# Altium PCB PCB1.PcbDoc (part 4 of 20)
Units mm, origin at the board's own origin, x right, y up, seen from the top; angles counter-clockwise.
Board outline 294.51 x 138.18 mm, 12 copper layers (Top Layer 1 _Signal, L2_GND, L3_Signals, L4_GND, L5_POWER, L6_Signals, L7_GND, L8_Signals, L9_GND, L10_POWER, L11_GND, Bottom Layer_Signals), stack 1.788 mm thick; 1254 components, 836 nets, 5699 pads, 2073 vias.
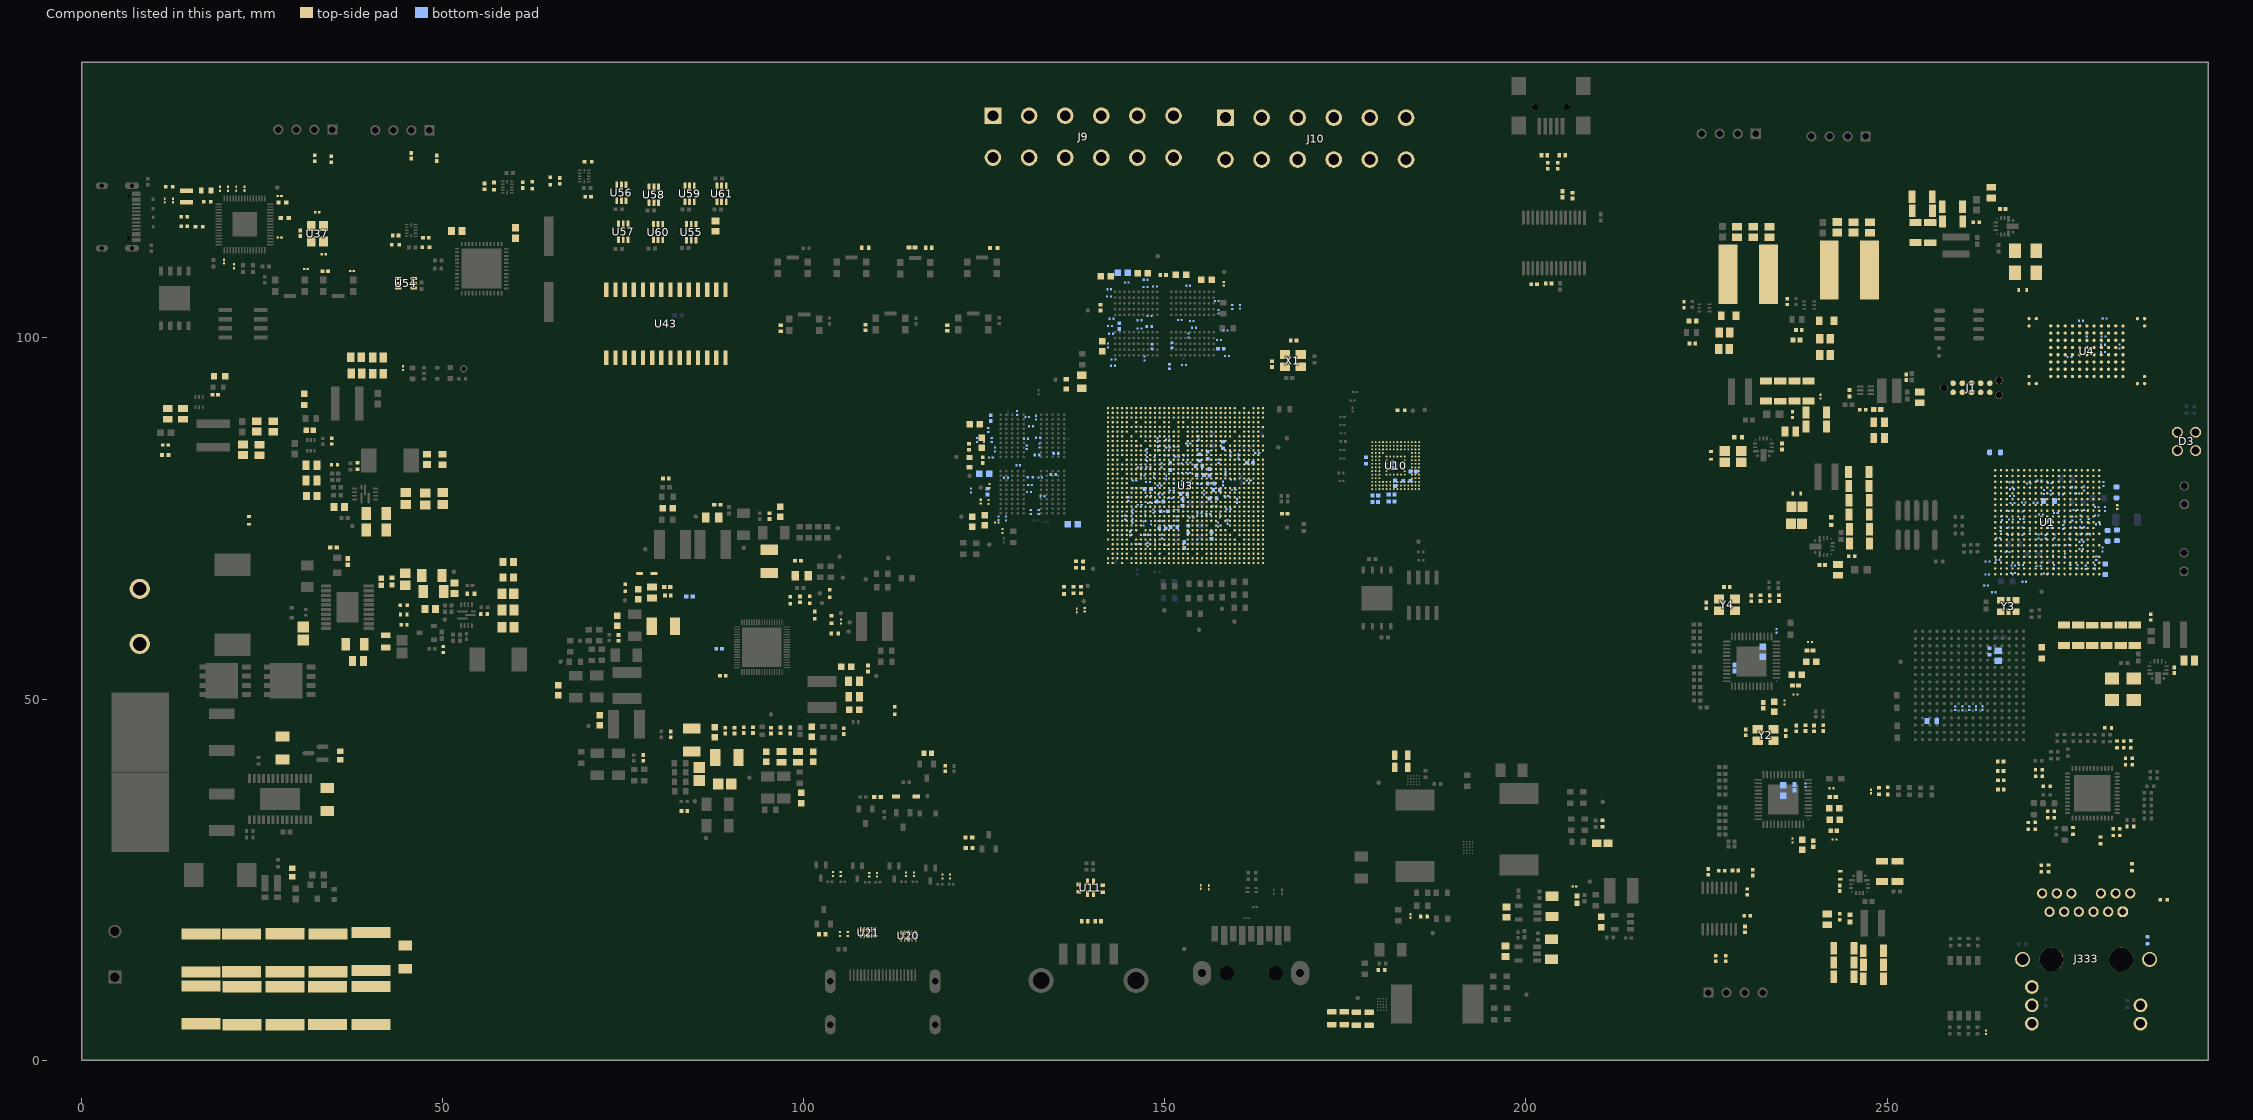
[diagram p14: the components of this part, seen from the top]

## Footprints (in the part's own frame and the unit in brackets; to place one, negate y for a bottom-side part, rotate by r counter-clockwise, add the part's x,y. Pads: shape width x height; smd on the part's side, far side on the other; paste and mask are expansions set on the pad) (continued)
BGA1088C65P34X34_2300X2300X204N [mm]
  round 0.32 smd mask-2539.97: A1(-10.725,10.725) A2(-10.075,10.725) A3(-9.425,10.725) A4(-8.775,10.725) A5(-8.125,10.725) A6(-7.475,10.725) A7(-6.825,10.725) A8(-6.175,10.725) A9(-5.525,10.725) A10(-4.875,10.725) A11(-4.225,10.725) A12(-3.575,10.725) A13(-2.925,10.725) A14(-2.275,10.725) A15(-1.625,10.725) A16(-0.975,10.725) A17(-0.325,10.725) A18(0.325,10.725) A19(0.975,10.725) A20(1.625,10.725) A21(2.275,10.725) A22(2.925,10.725) A23(3.575,10.725) A24(4.225,10.725) A25(4.875,10.725) A26(5.525,10.725) A27(6.175,10.725) A28(6.825,10.725) A30(8.125,10.725) A32(9.425,10.725) A33(10.075,10.725) A34(10.725,10.725) AA1(-10.725,-2.275) AA2(-10.075,-2.275) AA3(-9.425,-2.275) AA4(-8.775,-2.275) AA5(-8.125,-2.275) AA6(-7.475,-2.275) AA7(-6.825,-2.275) AA8(-6.175,-2.275) AA9(-5.525,-2.275) AA10(-4.875,-2.275) AA11(-4.225,-2.275) AA12(-3.575,-2.275) AA13(-2.925,-2.275) AA14(-2.275,-2.275) AA15(-1.625,-2.275) AA16(-0.975,-2.275) AA17(-0.325,-2.275) AA18(0.325,-2.275) AA19(0.975,-2.275) AA20(1.625,-2.275) AA21(2.275,-2.275) AA22(2.925,-2.275) AA23(3.575,-2.275) AA24(4.225,-2.275) AA25(4.875,-2.275) AA26(5.525,-2.275) AA27(6.175,-2.275) AA28(6.825,-2.275) AA29(7.475,-2.275) AA30(8.125,-2.275) AA31(8.775,-2.275) AA32(9.425,-2.275) AA33(10.075,-2.275) AA34(10.725,-2.275) AB1(-10.725,-2.925) AB2(-10.075,-2.925) AB3(-9.425,-2.925) AB4(-8.775,-2.925) AB5(-8.125,-2.925) AB6(-7.475,-2.925) AB7(-6.825,-2.925) AB8(-6.175,-2.925) AB9(-5.525,-2.925) AB10(-4.875,-2.925) AB11(-4.225,-2.925) AB12(-3.575,-2.925) AB13(-2.925,-2.925) AB14(-2.275,-2.925) AB15(-1.625,-2.925) AB16(-0.975,-2.925) AB17(-0.325,-2.925) AB18(0.325,-2.925) AB19(0.975,-2.925) AB20(1.625,-2.925) AB21(2.275,-2.925) AB22(2.925,-2.925) AB23(3.575,-2.925) AB24(4.225,-2.925) AB25(4.875,-2.925) AB26(5.525,-2.925) AB27(6.175,-2.925) AB28(6.825,-2.925) AB29(7.475,-2.925) AB30(8.125,-2.925) AB31(8.775,-2.925) AB32(9.425,-2.925) AB33(10.075,-2.925) AB34(10.725,-2.925) AC1(-10.725,-3.575) AC2(-10.075,-3.575) AC3(-9.425,-3.575) AC4(-8.775,-3.575) AC5(-8.125,-3.575) AC6(-7.475,-3.575) AC7(-6.825,-3.575) AC8(-6.175,-3.575) AC9(-5.525,-3.575) AC10(-4.875,-3.575) AC11(-4.225,-3.575) AC12(-3.575,-3.575) AC13(-2.925,-3.575) AC14(-2.275,-3.575) AC15(-1.625,-3.575) AC16(-0.975,-3.575) AC17(-0.325,-3.575) AC18(0.325,-3.575) AC19(0.975,-3.575) AC20(1.625,-3.575) AC21(2.275,-3.575) AC22(2.925,-3.575) AC23(3.575,-3.575) AC24(4.225,-3.575) AC25(4.875,-3.575) AC26(5.525,-3.575) AC27(6.175,-3.575) AC28(6.825,-3.575) AC29(7.475,-3.575) AC30(8.125,-3.575) AC31(8.775,-3.575) AC32(9.425,-3.575) AC33(10.075,-3.575) AC34(10.725,-3.575) AD1(-10.725,-4.225) AD2(-10.075,-4.225) AD3(-9.425,-4.225) AD4(-8.775,-4.225) AD5(-8.125,-4.225) AD6(-7.475,-4.225) AD7(-6.825,-4.225) AD8(-6.175,-4.225) AD9(-5.525,-4.225) AD10(-4.875,-4.225) AD11(-4.225,-4.225) AD12(-3.575,-4.225) AD13(-2.925,-4.225) AD14(-2.275,-4.225) AD15(-1.625,-4.225) AD16(-0.975,-4.225) AD17(-0.325,-4.225) AD18(0.325,-4.225) AD19(0.975,-4.225) AD20(1.625,-4.225) AD21(2.275,-4.225) AD22(2.925,-4.225) AD23(3.575,-4.225) AD24(4.225,-4.225) AD25(4.875,-4.225) AD26(5.525,-4.225) AD27(6.175,-4.225) AD28(6.825,-4.225) AD29(7.475,-4.225) AD30(8.125,-4.225) AD31(8.775,-4.225) AD32(9.425,-4.225) AD33(10.075,-4.225) AD34(10.725,-4.225) AE1(-10.725,-4.875) AE2(-10.075,-4.875) AE3(-9.425,-4.875) AE4(-8.775,-4.875) AE5(-8.125,-4.875) AE6(-7.475,-4.875) AE7(-6.825,-4.875) AE8(-6.175,-4.875) AE9(-5.525,-4.875) AE11(-4.225,-4.875) AE12(-3.575,-4.875) AE13(-2.925,-4.875) AE14(-2.275,-4.875) AE15(-1.625,-4.875) AE16(-0.975,-4.875) AE18(0.325,-4.875) AE19(0.975,-4.875) AE20(1.625,-4.875) AE21(2.275,-4.875) AE22(2.925,-4.875) AE23(3.575,-4.875) AE24(4.225,-4.875) AE26(5.525,-4.875) AE27(6.175,-4.875) AE28(6.825,-4.875) AE29(7.475,-4.875) AE30(8.125,-4.875) AE31(8.775,-4.875) AE32(9.425,-4.875) AE33(10.075,-4.875) AE34(10.725,-4.875) AF1(-10.725,-5.525) AF2(-10.075,-5.525) AF3(-9.425,-5.525) AF4(-8.775,-5.525) AF5(-8.125,-5.525) AF6(-7.475,-5.525) AF7(-6.825,-5.525) AF8(-6.175,-5.525) AF11(-4.225,-5.525) AF12(-3.575,-5.525) AF13(-2.925,-5.525) AF14(-2.275,-5.525) AF15(-1.625,-5.525) AF16(-0.975,-5.525) AF18(0.325,-5.525) AF19(0.975,-5.525) AF20(1.625,-5.525) AF21(2.275,-5.525) AF22(2.925,-5.525) AF24(4.225,-5.525) AF25(4.875,-5.525) AF27(6.175,-5.525) AF28(6.825,-5.525) AF29(7.475,-5.525) AF30(8.125,-5.525) AF31(8.775,-5.525) AF32(9.425,-5.525) AF33(10.075,-5.525) AF34(10.725,-5.525) AG1(-10.725,-6.175) AG2(-10.075,-6.175) AG3(-9.425,-6.175) AG4(-8.775,-6.175) AG5(-8.125,-6.175) AG6(-7.475,-6.175) AG7(-6.825,-6.175) AG9(-5.525,-6.175) AG10(-4.875,-6.175) AG11(-4.225,-6.175) AG12(-3.575,-6.175) AG13(-2.925,-6.175) AG14(-2.275,-6.175) AG15(-1.625,-6.175) AG16(-0.975,-6.175) AG18(0.325,-6.175) AG19(0.975,-6.175) AG20(1.625,-6.175) AG21(2.275,-6.175) AG22(2.925,-6.175) AG23(3.575,-6.175) AG24(4.225,-6.175) AG25(4.875,-6.175) AG26(5.525,-6.175) AG28(6.825,-6.175) AG29(7.475,-6.175) AG30(8.125,-6.175) AG31(8.775,-6.175) AG32(9.425,-6.175) AG33(10.075,-6.175) AG34(10.725,-6.175) AH2(-10.075,-6.825) AH3(-9.425,-6.825) AH4(-8.775,-6.825) AH5(-8.125,-6.825) AH6(-7.475,-6.825) AH8(-6.175,-6.825) AH9(-5.525,-6.825) AH10(-4.875,-6.825) AH11(-4.225,-6.825) AH12(-3.575,-6.825) AH13(-2.925,-6.825) AH14(-2.275,-6.825) AH15(-1.625,-6.825) AH16(-0.975,-6.825) AH18(0.325,-6.825) AH19(0.975,-6.825) AH20(1.625,-6.825) AH21(2.275,-6.825) AH22(2.925,-6.825) AH23(3.575,-6.825) AH24(4.225,-6.825) AH25(4.875,-6.825) AH26(5.525,-6.825) AH27(6.175,-6.825) AH29(7.475,-6.825) AH30(8.125,-6.825) AH31(8.775,-6.825) AH32(9.425,-6.825) AH33(10.075,-6.825) AH34(10.725,-6.825) AJ1(-10.725,-7.475) AJ2(-10.075,-7.475) AJ3(-9.425,-7.475) AJ4(-8.775,-7.475) AJ5(-8.125,-7.475) AJ7(-6.825,-7.475) AJ8(-6.175,-7.475) AJ9(-5.525,-7.475) AJ10(-4.875,-7.475) AJ11(-4.225,-7.475) AJ12(-3.575,-7.475) AJ13(-2.925,-7.475) AJ14(-2.275,-7.475) AJ15(-1.625,-7.475) AJ16(-0.975,-7.475) AJ18(0.325,-7.475) AJ19(0.975,-7.475) AJ20(1.625,-7.475) AJ21(2.275,-7.475) AJ22(2.925,-7.475) AJ23(3.575,-7.475) AJ24(4.225,-7.475) AJ25(4.875,-7.475) AJ26(5.525,-7.475) AJ27(6.175,-7.475) AJ28(6.825,-7.475) AJ30(8.125,-7.475) AJ31(8.775,-7.475) AJ32(9.425,-7.475) AJ33(10.075,-7.475) AJ34(10.725,-7.475) AK2(-10.075,-8.125) AK3(-9.425,-8.125) AK4(-8.775,-8.125) AK5(-8.125,-8.125) AK6(-7.475,-8.125) AK7(-6.825,-8.125) AK8(-6.175,-8.125) AK9(-5.525,-8.125) AK10(-4.875,-8.125) AK11(-4.225,-8.125) AK12(-3.575,-8.125) AK13(-2.925,-8.125) AK14(-2.275,-8.125) AK15(-1.625,-8.125) AK16(-0.975,-8.125) AK17(-0.325,-8.125) AK18(0.325,-8.125) AK19(0.975,-8.125) AK20(1.625,-8.125) AK21(2.275,-8.125) AK22(2.925,-8.125) AK23(3.575,-8.125) AK24(4.225,-8.125) AK25(4.875,-8.125) AK26(5.525,-8.125) AK27(6.175,-8.125) AK28(6.825,-8.125) AK29(7.475,-8.125) AK30(8.125,-8.125) AK31(8.775,-8.125) AK32(9.425,-8.125) AK33(10.075,-8.125) AK34(10.725,-8.125) AL1(-10.725,-8.775) AL2(-10.075,-8.775) AL3(-9.425,-8.775) AL4(-8.775,-8.775) AL5(-8.125,-8.775) AL6(-7.475,-8.775) AL7(-6.825,-8.775) AL8(-6.175,-8.775) AL9(-5.525,-8.775) AL10(-4.875,-8.775) AL11(-4.225,-8.775) AL12(-3.575,-8.775) AL13(-2.925,-8.775) AL14(-2.275,-8.775) AL15(-1.625,-8.775) AL16(-0.975,-8.775) AL17(-0.325,-8.775) AL18(0.325,-8.775) AL19(0.975,-8.775) AL20(1.625,-8.775) AL21(2.275,-8.775) AL22(2.925,-8.775) AL23(3.575,-8.775) AL24(4.225,-8.775) AL25(4.875,-8.775) AL26(5.525,-8.775) AL27(6.175,-8.775) AL28(6.825,-8.775) AL29(7.475,-8.775) AL30(8.125,-8.775) AL31(8.775,-8.775) AL32(9.425,-8.775) AL33(10.075,-8.775) AL34(10.725,-8.775) AM2(-10.075,-9.425) AM3(-9.425,-9.425) AM4(-8.775,-9.425) AM5(-8.125,-9.425) AM7(-6.825,-9.425) AM8(-6.175,-9.425) AM9(-5.525,-9.425) AM10(-4.875,-9.425) AM12(-3.575,-9.425) AM14(-2.275,-9.425) AM15(-1.625,-9.425) AM16(-0.975,-9.425) AM17(-0.325,-9.425) AM18(0.325,-9.425) AM20(1.625,-9.425) AM22(2.925,-9.425) AM23(3.575,-9.425) AM24(4.225,-9.425) AM25(4.875,-9.425) AM26(5.525,-9.425) AM27(6.175,-9.425) AM28(6.825,-9.425) AM29(7.475,-9.425) AM30(8.125,-9.425) AM31(8.775,-9.425) AM32(9.425,-9.425) AM33(10.075,-9.425) AM34(10.725,-9.425) AN1(-10.725,-10.075) AN2(-10.075,-10.075) AN3(-9.425,-10.075) AN4(-8.775,-10.075) AN5(-8.125,-10.075) AN6(-7.475,-10.075) AN7(-6.825,-10.075) AN8(-6.175,-10.075) AN9(-5.525,-10.075) AN10(-4.875,-10.075) AN11(-4.225,-10.075) AN12(-3.575,-10.075) AN13(-2.925,-10.075) AN14(-2.275,-10.075) AN15(-1.625,-10.075) AN16(-0.975,-10.075) AN17(-0.325,-10.075) AN18(0.325,-10.075) AN19(0.975,-10.075) AN20(1.625,-10.075) AN21(2.275,-10.075) AN22(2.925,-10.075) AN23(3.575,-10.075) AN24(4.225,-10.075) AN25(4.875,-10.075) AN26(5.525,-10.075) AN27(6.175,-10.075) AN28(6.825,-10.075) AN29(7.475,-10.075) AN30(8.125,-10.075) AN31(8.775,-10.075) AN32(9.425,-10.075) AN33(10.075,-10.075) AN34(10.725,-10.075) AP1(-10.725,-10.725) AP2(-10.075,-10.725) AP4(-8.775,-10.725) AP6(-7.475,-10.725) AP7(-6.825,-10.725) AP8(-6.175,-10.725) AP9(-5.525,-10.725) AP10(-4.875,-10.725) AP11(-4.225,-10.725) AP12(-3.575,-10.725) AP13(-2.925,-10.725) AP14(-2.275,-10.725) AP15(-1.625,-10.725) AP16(-0.975,-10.725) AP17(-0.325,-10.725) AP18(0.325,-10.725) AP19(0.975,-10.725) AP20(1.625,-10.725) AP21(2.275,-10.725) AP22(2.925,-10.725) AP23(3.575,-10.725) AP24(4.225,-10.725) AP25(4.875,-10.725) AP26(5.525,-10.725) AP27(6.175,-10.725) AP28(6.825,-10.725) AP29(7.475,-10.725) AP30(8.125,-10.725) AP31(8.775,-10.725) AP32(9.425,-10.725) AP33(10.075,-10.725) AP34(10.725,-10.725) B1(-10.725,10.075) B2(-10.075,10.075) B3(-9.425,10.075) B4(-8.775,10.075) B5(-8.125,10.075) B6(-7.475,10.075) B7(-6.825,10.075) B8(-6.175,10.075) B9(-5.525,10.075) B10(-4.875,10.075) B11(-4.225,10.075) B12(-3.575,10.075) B13(-2.925,10.075) B14(-2.275,10.075) B15(-1.625,10.075) B16(-0.975,10.075) B17(-0.325,10.075) B18(0.325,10.075) B19(0.975,10.075) B20(1.625,10.075) B21(2.275,10.075) B22(2.925,10.075) B23(3.575,10.075) B24(4.225,10.075) B25(4.875,10.075) B26(5.525,10.075) B27(6.175,10.075) B28(6.825,10.075) B29(7.475,10.075) B30(8.125,10.075) B31(8.775,10.075) B32(9.425,10.075) B33(10.075,10.075) B34(10.725,10.075) C1(-10.725,9.425) C2(-10.075,9.425) C3(-9.425,9.425) C4(-8.775,9.425) C5(-8.125,9.425) C6(-7.475,9.425) C7(-6.825,9.425) C8(-6.175,9.425) C9(-5.525,9.425) C10(-4.875,9.425) C11(-4.225,9.425) C12(-3.575,9.425) C13(-2.925,9.425) C14(-2.275,9.425) C15(-1.625,9.425) C16(-0.975,9.425) C17(-0.325,9.425) C18(0.325,9.425) C19(0.975,9.425) C20(1.625,9.425) C21(2.275,9.425) C22(2.925,9.425) C23(3.575,9.425) C24(4.225,9.425) C25(4.875,9.425) C26(5.525,9.425) C27(6.175,9.425) C28(6.825,9.425) C29(7.475,9.425) C30(8.125,9.425) C31(8.775,9.425) C32(9.425,9.425) C33(10.075,9.425) C34(10.725,9.425) D1(-10.725,8.775) D2(-10.075,8.775) D3(-9.425,8.775) D4(-8.775,8.775) D5(-8.125,8.775) D7(-6.825,8.775) D9(-5.525,8.775) D10(-4.875,8.775) D11(-4.225,8.775) D13(-2.925,8.775) D14(-2.275,8.775) D16(-0.975,8.775) D17(-0.325,8.775) D19(0.975,8.775) D20(1.625,8.775) D21(2.275,8.775) D22(2.925,8.775) D23(3.575,8.775) D24(4.225,8.775) D25(4.875,8.775) D26(5.525,8.775) D27(6.175,8.775) D28(6.825,8.775) D29(7.475,8.775) D30(8.125,8.775) D31(8.775,8.775) D32(9.425,8.775) D33(10.075,8.775) E1(-10.725,8.125) E2(-10.075,8.125) E3(-9.425,8.125) E4(-8.775,8.125) E5(-8.125,8.125) E6(-7.475,8.125) E7(-6.825,8.125) E8(-6.175,8.125) E9(-5.525,8.125) E10(-4.875,8.125) E11(-4.225,8.125) E12(-3.575,8.125) E13(-2.925,8.125) E14(-2.275,8.125) E16(-0.975,8.125) E17(-0.325,8.125) E18(0.325,8.125) E19(0.975,8.125) E20(1.625,8.125) E21(2.275,8.125) E22(2.925,8.125) E23(3.575,8.125) E24(4.225,8.125) E25(4.875,8.125) E26(5.525,8.125) E27(6.175,8.125) E28(6.825,8.125) E29(7.475,8.125) E30(8.125,8.125) E31(8.775,8.125) E32(9.425,8.125) E33(10.075,8.125) E34(10.725,8.125) F1(-10.725,7.475) F2(-10.075,7.475) F3(-9.425,7.475) F4(-8.775,7.475) F5(-8.125,7.475) F7(-6.825,7.475) F8(-6.175,7.475) F9(-5.525,7.475) F10(-4.875,7.475) F11(-4.225,7.475) F12(-3.575,7.475) F13(-2.925,7.475) F14(-2.275,7.475) F15(-1.625,7.475) F16(-0.975,7.475) F18(0.325,7.475) F19(0.975,7.475) F20(1.625,7.475) F21(2.275,7.475) F22(2.925,7.475) F23(3.575,7.475) F24(4.225,7.475) F25(4.875,7.475) F26(5.525,7.475) F27(6.175,7.475) F28(6.825,7.475) F30(8.125,7.475) F31(8.775,7.475) F32(9.425,7.475) F33(10.075,7.475) G1(-10.725,6.825) G2(-10.075,6.825) G3(-9.425,6.825) G4(-8.775,6.825) G6(-7.475,6.825) G8(-6.175,6.825) G9(-5.525,6.825) G10(-4.875,6.825) G11(-4.225,6.825) G12(-3.575,6.825) G13(-2.925,6.825) G14(-2.275,6.825) G15(-1.625,6.825) G16(-0.975,6.825) G18(0.325,6.825) G19(0.975,6.825) G20(1.625,6.825) G21(2.275,6.825) G22(2.925,6.825) G23(3.575,6.825) G24(4.225,6.825) G25(4.875,6.825) G26(5.525,6.825) G27(6.175,6.825) G29(7.475,6.825) G30(8.125,6.825) G31(8.775,6.825) G32(9.425,6.825) G33(10.075,6.825) G34(10.725,6.825) H1(-10.725,6.175) H2(-10.075,6.175) H3(-9.425,6.175) H4(-8.775,6.175) H5(-8.125,6.175) H6(-7.475,6.175) H7(-6.825,6.175) H9(-5.525,6.175) H10(-4.875,6.175) H11(-4.225,6.175) H12(-3.575,6.175) H13(-2.925,6.175) H14(-2.275,6.175) H15(-1.625,6.175) H16(-0.975,6.175) H18(0.325,6.175) H19(0.975,6.175) H20(1.625,6.175) H21(2.275,6.175) H22(2.925,6.175) H23(3.575,6.175) H24(4.225,6.175) H25(4.875,6.175) H26(5.525,6.175) H28(6.825,6.175) H29(7.475,6.175) H30(8.125,6.175) H31(8.775,6.175) H32(9.425,6.175) H33(10.075,6.175) J1(-10.725,5.525) J2(-10.075,5.525) J3(-9.425,5.525) J4(-8.775,5.525) J5(-8.125,5.525) J6(-7.475,5.525) J7(-6.825,5.525) J8(-6.175,5.525) J10(-4.875,5.525) J11(-4.225,5.525) J12(-3.575,5.525) J13(-2.925,5.525) J14(-2.275,5.525) J15(-1.625,5.525) J16(-0.975,5.525) J18(0.325,5.525) J19(0.975,5.525) J20(1.625,5.525) J21(2.275,5.525) J22(2.925,5.525) J23(3.575,5.525) J24(4.225,5.525) J25(4.875,5.525) J27(6.175,5.525) J28(6.825,5.525) J29(7.475,5.525) J30(8.125,5.525) J31(8.775,5.525) J32(9.425,5.525) J33(10.075,5.525) J34(10.725,5.525) K1(-10.725,4.875) K2(-10.075,4.875) K3(-9.425,4.875) K4(-8.775,4.875) K5(-8.125,4.875) K6(-7.475,4.875) K7(-6.825,4.875) K8(-6.175,4.875) K9(-5.525,4.875) K11(-4.225,4.875) K12(-3.575,4.875) K13(-2.925,4.875) K14(-2.275,4.875) K15(-1.625,4.875) K16(-0.975,4.875) K18(0.325,4.875) K19(0.975,4.875) K20(1.625,4.875) K21(2.275,4.875) K22(2.925,4.875) K23(3.575,4.875) K24(4.225,4.875) K26(5.525,4.875) K27(6.175,4.875) K28(6.825,4.875) K29(7.475,4.875) K30(8.125,4.875) K31(8.775,4.875) K32(9.425,4.875) K33(10.075,4.875) K34(10.725,4.875) L1(-10.725,4.225) L2(-10.075,4.225) L3(-9.425,4.225) L4(-8.775,4.225) L5(-8.125,4.225) L6(-7.475,4.225) L7(-6.825,4.225) L8(-6.175,4.225) L9(-5.525,4.225) L10(-4.875,4.225) L11(-4.225,4.225) L12(-3.575,4.225) L13(-2.925,4.225) L14(-2.275,4.225) L15(-1.625,4.225) L16(-0.975,4.225) L17(-0.325,4.225) L18(0.325,4.225) L19(0.975,4.225) L20(1.625,4.225) L21(2.275,4.225) L22(2.925,4.225) L23(3.575,4.225) L24(4.225,4.225) L25(4.875,4.225) L26(5.525,4.225) L27(6.175,4.225) L28(6.825,4.225) L29(7.475,4.225) L30(8.125,4.225) L31(8.775,4.225) L32(9.425,4.225) L33(10.075,4.225) M1(-10.725,3.575) M2(-10.075,3.575) M3(-9.425,3.575) M5(-8.125,3.575) M6(-7.475,3.575) M7(-6.825,3.575) M8(-6.175,3.575) M9(-5.525,3.575) M10(-4.875,3.575) M11(-4.225,3.575) M12(-3.575,3.575) M13(-2.925,3.575) M14(-2.275,3.575) M15(-1.625,3.575) M16(-0.975,3.575) M17(-0.325,3.575) M18(0.325,3.575) M19(0.975,3.575) M20(1.625,3.575) M21(2.275,3.575) M22(2.925,3.575) M23(3.575,3.575) M24(4.225,3.575) M25(4.875,3.575) M26(5.525,3.575) M27(6.175,3.575) M28(6.825,3.575) M29(7.475,3.575) M30(8.125,3.575) M31(8.775,3.575) M32(9.425,3.575) M33(10.075,3.575) M34(10.725,3.575) N1(-10.725,2.925) N2(-10.075,2.925) N3(-9.425,2.925) N4(-8.775,2.925) N5(-8.125,2.925) N6(-7.475,2.925) N7(-6.825,2.925) N8(-6.175,2.925) N9(-5.525,2.925) N10(-4.875,2.925) N11(-4.225,2.925) N12(-3.575,2.925) N13(-2.925,2.925) N14(-2.275,2.925) N15(-1.625,2.925) N16(-0.975,2.925) N17(-0.325,2.925) N18(0.325,2.925) N19(0.975,2.925) N20(1.625,2.925) N21(2.275,2.925) N22(2.925,2.925) N23(3.575,2.925) N24(4.225,2.925) N25(4.875,2.925) N26(5.525,2.925) N27(6.175,2.925) N28(6.825,2.925) N29(7.475,2.925) N30(8.125,2.925) N31(8.775,2.925) N32(9.425,2.925) N33(10.075,2.925) N34(10.725,2.925) P1(-10.725,2.275) P2(-10.075,2.275) P3(-9.425,2.275) P4(-8.775,2.275) P5(-8.125,2.275) P6(-7.475,2.275) P7(-6.825,2.275) P8(-6.175,2.275) P9(-5.525,2.275) P10(-4.875,2.275) P11(-4.225,2.275) P12(-3.575,2.275) P13(-2.925,2.275) P14(-2.275,2.275) P15(-1.625,2.275) P16(-0.975,2.275) P17(-0.325,2.275) P18(0.325,2.275) P19(0.975,2.275) P20(1.625,2.275) P21(2.275,2.275) P22(2.925,2.275) P23(3.575,2.275) P24(4.225,2.275) P25(4.875,2.275) P26(5.525,2.275) P27(6.175,2.275) P28(6.825,2.275) P29(7.475,2.275) P30(8.125,2.275) P31(8.775,2.275) P32(9.425,2.275) P33(10.075,2.275) P34(10.725,2.275) R1(-10.725,1.625) R2(-10.075,1.625) R3(-9.425,1.625) R5(-8.125,1.625) R6(-7.475,1.625) R7(-6.825,1.625) R8(-6.175,1.625) R9(-5.525,1.625) R10(-4.875,1.625) R11(-4.225,1.625) R12(-3.575,1.625) R13(-2.925,1.625) R14(-2.275,1.625) R15(-1.625,1.625) R16(-0.975,1.625) R17(-0.325,1.625) R18(0.325,1.625) R19(0.975,1.625) R20(1.625,1.625) R21(2.275,1.625) R22(2.925,1.625) R23(3.575,1.625) R24(4.225,1.625) R25(4.875,1.625) R26(5.525,1.625) R27(6.175,1.625) R28(6.825,1.625) R29(7.475,1.625) R30(8.125,1.625) R31(8.775,1.625) R32(9.425,1.625) R33(10.075,1.625) R34(10.725,1.625) T1(-10.725,0.975) T2(-10.075,0.975) T3(-9.425,0.975) T4(-8.775,0.975) T5(-8.125,0.975) T6(-7.475,0.975) T7(-6.825,0.975) T8(-6.175,0.975) T9(-5.525,0.975) T10(-4.875,0.975) T11(-4.225,0.975) T12(-3.575,0.975) T13(-2.925,0.975) T14(-2.275,0.975) T15(-1.625,0.975) T16(-0.975,0.975) T17(-0.325,0.975) T18(0.325,0.975) T19(0.975,0.975) T20(1.625,0.975) T21(2.275,0.975) T22(2.925,0.975) T23(3.575,0.975) T24(4.225,0.975) T25(4.875,0.975) T26(5.525,0.975) T27(6.175,0.975) T28(6.825,0.975) T29(7.475,0.975) T30(8.125,0.975) T31(8.775,0.975) T32(9.425,0.975) T33(10.075,0.975) T34(10.725,0.975) U1(-10.725,0.325) U2(-10.075,0.325) U3(-9.425,0.325) U4(-8.775,0.325) U5(-8.125,0.325) U11(-4.225,0.325) U12(-3.575,0.325) U13(-2.925,0.325) U14(-2.275,0.325) U15(-1.625,0.325) U16(-0.975,0.325) U17(-0.325,0.325) U18(0.325,0.325) U19(0.975,0.325) U20(1.625,0.325) U21(2.275,0.325) U22(2.925,0.325) U23(3.575,0.325) U24(4.225,0.325) U30(8.125,0.325) U31(8.775,0.325) U32(9.425,0.325) U33(10.075,0.325) U34(10.725,0.325) V1(-10.725,-0.325) V2(-10.075,-0.325) V3(-9.425,-0.325) V4(-8.775,-0.325) V5(-8.125,-0.325) V6(-7.475,-0.325) V7(-6.825,-0.325) V8(-6.175,-0.325) V9(-5.525,-0.325) V10(-4.875,-0.325) V11(-4.225,-0.325) V12(-3.575,-0.325) V13(-2.925,-0.325) V14(-2.275,-0.325) V15(-1.625,-0.325) V16(-0.975,-0.325) V17(-0.325,-0.325) V18(0.325,-0.325) V19(0.975,-0.325) V20(1.625,-0.325) V21(2.275,-0.325) V22(2.925,-0.325) V23(3.575,-0.325) V24(4.225,-0.325) V25(4.875,-0.325) V26(5.525,-0.325) V27(6.175,-0.325) V28(6.825,-0.325) V29(7.475,-0.325) V30(8.125,-0.325) V31(8.775,-0.325) V32(9.425,-0.325) V33(10.075,-0.325) V34(10.725,-0.325) W1(-10.725,-0.975) W2(-10.075,-0.975) W3(-9.425,-0.975) W4(-8.775,-0.975) W5(-8.125,-0.975) W6(-7.475,-0.975) W7(-6.825,-0.975) W8(-6.175,-0.975) W9(-5.525,-0.975) W10(-4.875,-0.975) W11(-4.225,-0.975) W12(-3.575,-0.975) W13(-2.925,-0.975) W14(-2.275,-0.975) W15(-1.625,-0.975) W16(-0.975,-0.975) W17(-0.325,-0.975) W18(0.325,-0.975) W19(0.975,-0.975) W20(1.625,-0.975) W21(2.275,-0.975) W22(2.925,-0.975) W23(3.575,-0.975) W24(4.225,-0.975) W25(4.875,-0.975) W26(5.525,-0.975) W27(6.175,-0.975) W28(6.825,-0.975) W29(7.475,-0.975) W30(8.125,-0.975) W31(8.775,-0.975) W32(9.425,-0.975) W33(10.075,-0.975) W34(10.725,-0.975) Y1(-10.725,-1.625) Y2(-10.075,-1.625) Y3(-9.425,-1.625) Y4(-8.775,-1.625) Y5(-8.125,-1.625) Y6(-7.475,-1.625) Y7(-6.825,-1.625) Y8(-6.175,-1.625) Y9(-5.525,-1.625) Y10(-4.875,-1.625) Y11(-4.225,-1.625) Y12(-3.575,-1.625) Y13(-2.925,-1.625) Y14(-2.275,-1.625) Y15(-1.625,-1.625) Y16(-0.975,-1.625) Y17(-0.325,-1.625) Y18(0.325,-1.625) Y19(0.975,-1.625) Y20(1.625,-1.625) Y21(2.275,-1.625) Y22(2.925,-1.625) Y23(3.575,-1.625) Y24(4.225,-1.625) Y26(5.525,-1.625) Y27(6.175,-1.625) Y28(6.825,-1.625) Y29(7.475,-1.625) Y30(8.125,-1.625) Y31(8.775,-1.625) Y32(9.425,-1.625) Y33(10.075,-1.625) Y34(10.725,-1.625)
  silkscreen extent -12.2,-11.5 11.5,11.5, body extent -11.5,-11.5 11.5,11.5, height 2.04
BGA-356_P0.8_17x17x1.68 [mil] "BGA, 356-Leads, Body 17.00x17.00mmx1.68mm, Pitch 0.80mm"
  round 13 smd paste+0 mask+1: A1(-283.46,283.46) A2(-251.97,283.46) A3(-220.47,283.46) A4(-188.98,283.46) A5(-157.48,283.46) A6(-125.98,283.46) A8(-62.99,283.46) A10(0,283.46) A12(62.99,283.46) A14(125.98,283.46) A16(188.98,283.46) A17(220.47,283.46) A18(251.97,283.46) A19(283.46,283.46) B1(-283.46,251.97) B2(-251.97,251.97) B3(-220.47,251.97) B4(-188.98,251.97) B5(-157.48,251.97) B6(-125.98,251.97) B7(-94.49,251.97) B8(-62.99,251.97) B9(-31.5,251.97) B10(0,251.97) B11(31.5,251.97) B12(62.99,251.97) B13(94.49,251.97) B14(125.98,251.97) B15(157.48,251.97) B16(188.98,251.97) B17(220.47,251.97) B18(251.97,251.97) B19(283.46,251.97) C1(-283.46,220.47) C2(-251.97,220.47) C3(-220.47,220.47) C4(-188.98,220.47) C5(-157.48,220.47) C6(-125.98,220.47) C7(-94.49,220.47) C8(-62.99,220.47) C9(-31.5,220.47) C10(0,220.47) C11(31.5,220.47) C12(62.99,220.47) C13(94.49,220.47) C14(125.98,220.47) C15(157.48,220.47) C16(188.98,220.47) C17(220.47,220.47) C18(251.97,220.47) C19(283.46,220.47) D1(-283.46,188.98) D2(-251.97,188.98) D3(-220.47,188.98) D4(-188.98,188.98) D5(-157.48,188.98) D6(-125.98,188.98) D7(-94.49,188.98) D8(-62.99,188.98) D9(-31.5,188.98) D10(0,188.98) D11(31.5,188.98) D12(62.99,188.98) D13(94.49,188.98) D14(125.98,188.98) D15(157.48,188.98) D16(188.98,188.98) D17(220.47,188.98) D18(251.97,188.98) D19(283.46,188.98) E1(-283.46,157.48) E2(-251.97,157.48) E3(-220.47,157.48) E4(-188.98,157.48) E5(-157.48,157.48) E6(-125.98,157.48) E7(-94.49,157.48) E8(-62.99,157.48) E9(-31.5,157.48) E10(0,157.48) E11(31.5,157.48) E12(62.99,157.48) E13(94.49,157.48) E14(125.98,157.48) E15(157.48,157.48) E16(188.98,157.48) E17(220.47,157.48) E18(251.97,157.48) E19(283.46,157.48) F1(-283.46,125.98) F2(-251.97,125.98) F3(-220.47,125.98) F4(-188.98,125.98) F5(-157.48,125.98) F6(-125.98,125.98) F7(-94.49,125.98) F8(-62.99,125.98) F9(-31.5,125.98) F10(0,125.98) F11(31.5,125.98) F12(62.99,125.98) F13(94.49,125.98) F14(125.98,125.98) F15(157.48,125.98) F16(188.98,125.98) F17(220.47,125.98) F18(251.97,125.98) F19(283.46,125.98) G1(-283.46,94.49) G2(-251.97,94.49) G3(-220.47,94.49) G4(-188.98,94.49) G5(-157.48,94.49) G6(-125.98,94.49) G7(-94.49,94.49) G8(-62.99,94.49) G9(-31.5,94.49) G10(0,94.49) G11(31.5,94.49) G12(62.99,94.49) G13(94.49,94.49) G14(125.98,94.49) G15(157.48,94.49) G16(188.98,94.49) G17(220.47,94.49) G18(251.97,94.49) G19(283.46,94.49) H1(-283.46,62.99) H2(-251.97,62.99) H3(-220.47,62.99) H4(-188.98,62.99) H5(-157.48,62.99) H6(-125.98,62.99) H7(-94.49,62.99) H8(-62.99,62.99) H9(-31.5,62.99) H10(0,62.99) H11(31.5,62.99) H12(62.99,62.99) H13(94.49,62.99) H14(125.98,62.99) H15(157.48,62.99) H16(188.98,62.99) H17(220.47,62.99) H18(251.97,62.99) H19(283.46,62.99) J1(-283.46,31.5) J2(-251.97,31.5) J3(-220.47,31.5) J4(-188.98,31.5) J5(-157.48,31.5) J6(-125.98,31.5) J7(-94.49,31.5) J8(-62.99,31.5) J9(-31.5,31.5) J10(0,31.5) J11(31.5,31.5) J12(62.99,31.5) J13(94.49,31.5) J14(125.98,31.5) J15(157.48,31.5) J16(188.98,31.5) J17(220.47,31.5) J18(251.97,31.5) J19(283.46,31.5) K1(-283.46,0) K2(-251.97,0) K3(-220.47,0) K4(-188.98,0) K5(-157.48,0) K6(-125.98,0) K7(-94.49,0) K8(-62.99,0) K9(-31.5,0) K10(0,0) K11(31.5,0) K12(62.99,0) K13(94.49,0) K14(125.98,0) K15(157.48,0) K16(188.98,0) K17(220.47,0) K18(251.97,0) K19(283.46,0) L1(-283.46,-31.5) L2(-251.97,-31.5) L3(-220.47,-31.5) L4(-188.98,-31.5) L5(-157.48,-31.5) L6(-125.98,-31.5) L7(-94.49,-31.5) L8(-62.99,-31.5) L9(-31.5,-31.5) L10(0,-31.5) L11(31.5,-31.5) L12(62.99,-31.5) L13(94.49,-31.5) L14(125.98,-31.5) L15(157.48,-31.5) L16(188.98,-31.5) L17(220.47,-31.5) L18(251.97,-31.5) L19(283.46,-31.5) M1(-283.46,-62.99) M2(-251.97,-62.99) M3(-220.47,-62.99) M4(-188.98,-62.99) M5(-157.48,-62.99) M6(-125.98,-62.99) M7(-94.49,-62.99) M8(-62.99,-62.99) M9(-31.5,-62.99) M10(0,-62.99) M11(31.5,-62.99) M12(62.99,-62.99) M13(94.49,-62.99) M14(125.98,-62.99) M15(157.48,-62.99) M16(188.98,-62.99) M17(220.47,-62.99) M18(251.97,-62.99) M19(283.46,-62.99) N1(-283.46,-94.49) N2(-251.97,-94.49) N3(-220.47,-94.49) N4(-188.98,-94.49) N5(-157.48,-94.49) N6(-125.98,-94.49) N7(-94.49,-94.49) N8(-62.99,-94.49) N9(-31.5,-94.49) N10(0,-94.49) N11(31.5,-94.49) N12(62.99,-94.49) N13(94.49,-94.49) N14(125.98,-94.49) N15(157.48,-94.49) N16(188.98,-94.49) N17(220.47,-94.49) N18(251.97,-94.49) N19(283.46,-94.49) P1(-283.46,-125.98) P2(-251.97,-125.98) P3(-220.47,-125.98) P4(-188.98,-125.98) P5(-157.48,-125.98) P6(-125.98,-125.98) P7(-94.49,-125.98) P8(-62.99,-125.98) P9(-31.5,-125.98) P10(0,-125.98) P11(31.5,-125.98) P12(62.99,-125.98) P13(94.49,-125.98) P14(125.98,-125.98) P15(157.48,-125.98) P16(188.98,-125.98) P17(220.47,-125.98) P18(251.97,-125.98) P19(283.46,-125.98) R1(-283.46,-157.48) R2(-251.97,-157.48) R3(-220.47,-157.48) R4(-188.98,-157.48) R5(-157.48,-157.48) R6(-125.98,-157.48) R7(-94.49,-157.48) R8(-62.99,-157.48) R9(-31.5,-157.48) R10(0,-157.48) R11(31.5,-157.48) R12(62.99,-157.48) R13(94.49,-157.48) R14(125.98,-157.48) R15(157.48,-157.48) R16(188.98,-157.48) R17(220.47,-157.48) R18(251.97,-157.48) R19(283.46,-157.48) T1(-283.46,-188.98) T2(-251.97,-188.98) T3(-220.47,-188.98) T4(-188.98,-188.98) T5(-157.48,-188.98) T6(-125.98,-188.98) T7(-94.49,-188.98) T8(-62.99,-188.98) T9(-31.5,-188.98) T10(0,-188.98) T11(31.5,-188.98) T12(62.99,-188.98) T13(94.49,-188.98) T14(125.98,-188.98) T15(157.48,-188.98) T16(188.98,-188.98) T17(220.47,-188.98) T18(251.97,-188.98) T19(283.46,-188.98) U1(-283.46,-220.47) U2(-251.97,-220.47) U3(-220.47,-220.47) U4(-188.98,-220.47) U5(-157.48,-220.47) U6(-125.98,-220.47) U7(-94.49,-220.47) U8(-62.99,-220.47) U9(-31.5,-220.47) U10(0,-220.47) U11(31.5,-220.47) U12(62.99,-220.47) U13(94.49,-220.47) U14(125.98,-220.47) U15(157.48,-220.47) U16(188.98,-220.47) U17(220.47,-220.47) U18(251.97,-220.47) U19(283.46,-220.47) V1(-283.46,-251.97) V2(-251.97,-251.97) V3(-220.47,-251.97) V4(-188.98,-251.97) V5(-157.48,-251.97) V6(-125.98,-251.97) V7(-94.49,-251.97) V8(-62.99,-251.97) V9(-31.5,-251.97) V10(0,-251.97) V11(31.5,-251.97) V12(62.99,-251.97) V13(94.49,-251.97) V14(125.98,-251.97) V15(157.48,-251.97) V16(188.98,-251.97) V17(220.47,-251.97) V18(251.97,-251.97) V19(283.46,-251.97) W1(-283.46,-283.46) W2(-251.97,-283.46) W3(-220.47,-283.46) W4(-188.98,-283.46) W5(-157.48,-283.46) W6(-125.98,-283.46) W7(-94.49,-283.46) W8(-62.99,-283.46) W9(-31.5,-283.46) W10(0,-283.46) W11(31.5,-283.46) W12(62.99,-283.46) W13(94.49,-283.46) W14(125.98,-283.46) W15(157.48,-283.46) W16(188.98,-283.46) W17(220.47,-283.46) W18(251.97,-283.46) W19(283.46,-283.46)
  silkscreen extent -344,-343 343,344, body extent -335,-335 335,335, height 66
BOUR-SRN8040_V [mm] "SMD, 2-Leads, Body 8x8mm"
  rect 2.6x8.2 smd: 1(-2.8,0) 2(2.8,0)
  silkscreen extent -1.1,-4 1.1,4, body extent -4.01,-4 4.01,4, height 4
CAP_C_0201 [mm] "Chip Capacitor, 2-Leads, Body 0.6x0.3mm, IPC Medium Density"
  rrect40% 0.28x0.28 smd mask+0.05: 1(-0.27,0) 2(0.27,0)
  body extent -0.3,-0.15 0.3,0.15, height 0.28
CAP_C_0402 [mil] "Chip Capacitor 2-Leads, Body 1.6x0.8mm, IPC Medium Density"
  rrect33% 18.7x20 smd mask+2: 1(-18.69,0) 2(18.66,-0.07)
  silkscreen extent -4,-10 4,10, body extent -20,-10 20,10, height 19
CAP_C_0603 [mm] "Chip Capacitor, 2-Leads, Body 1.6x0.8mm, IPC Medium Density"
  rrect50% 0.7x0.8 smd: 1(-0.75,0) 2(0.75,0)
  silkscreen extent -0.1,-0.37 0.1,0.38, body extent -0.8,-0.4 0.8,0.4, height 0.65
CAPC0402(1005)60_L [mm] "Chip Capacitor, Body 1.0x0.5mm, Height 0.6mm, IPC High Density"
  rrect25% 0.5x0.55 smd: 1(-0.45,0) 2(0.45,0)
  silkscreen extent 0,-0.2 0,0.2, body extent -0.5,-0.25 0.5,0.25, height 0.6
CAPC0805(2012)145_L [mm] "Chip Capacitor, Body 2.0x1.2mm, Height 1.45mm, IPC High Density"
  rrect25% 0.76x1.3 smd: 1(-0.9,0) 2(0.89,0)
  silkscreen extent -0.3,-0.55 0.3,0.55, body extent -1,-0.6 1,0.6, height 1.45
CAPC1005X55X25LL05T05 [mm] "Chip Capacitor, 2-Leads, Body 1.00x0.50mm, IPC High Density"
  rect 0.52x0.52 smd: 1(-0.41,0) 2(0.41,0)
  body extent -0.53,-0.28 0.53,0.28, height 0.55
CAPC1005X55X25LL05T10 [mm] "Chip Capacitor, 2-Leads, Body 1.05x0.55mm, IPC High Density"
  rect 0.56x0.52 smd: 1(-0.39,0) 2(0.39,0)
  body extent -0.53,-0.28 0.53,0.28, height 0.55
CAPC1005X55X25ML05T05 [mm] "Chip Capacitor, 2-Leads, Body 1.00x0.50mm, IPC Low Density"
  rect 0.72x0.72 smd: 1(-0.51,0) 2(0.51,0)
  body extent -0.53,-0.28 0.53,0.27, height 0.55
CAPC1005X55X25ML05T10 [mm] "Chip Capacitor, 2-Leads, Body 1.00x0.50mm, IPC Low Density"
  rect 0.76x0.72 smd: 1(-0.49,0) 2(0.49,0)
  body extent -0.53,-0.28 0.53,0.27, height 0.55
CAPC1005X55X25NL05T10 [mm] "Chip Capacitor, 2-Leads, Body 1.00x0.50mm, IPC Medium Density"
  rect 0.66x0.62 smd: 1(-0.44,0) 2(0.44,0)
  body extent -0.53,-0.28 0.53,0.27, height 0.55
CAPC1005X55X30LL05T10 [mm] "Chip Capacitor, 2-Leads, Body 1.05x0.55mm, IPC High Density"
  rect 0.56x0.52 smd: 1(-0.38,0) 2(0.38,0)
  body extent -0.53,-0.28 0.53,0.28, height 0.55
CAPC1005X55X30ML05T10 [mm] "Chip Capacitor, 2-Leads, Body 1.00x0.50mm, IPC Low Density"
  rect 0.76x0.72 smd: 1(-0.48,0) 2(0.48,0)
  body extent -0.53,-0.28 0.53,0.27, height 0.55
CAPC1005X56X25LL10T15 [mm] "Chip Capacitor, 2-Leads, Body 1.00x0.50mm, IPC High Density"
  rect 0.58x0.54 smd: 1(-0.39,0) 2(0.39,0)
  body extent -0.55,-0.3 0.55,0.3, height 0.56
CAPC1206(3216)190_L [mm] "Chip Capacitor, Body 3.2x1.6mm, Height 1.9mm, IPC High Density"
  rect 0.95x1.7 smd: 1(-1.4,0) 2(1.4,0)
  silkscreen extent -0.55,-0.75 0.55,0.75, body extent -1.7,-0.9 1.7,0.9, height 1.9
CAPC1206(3216)190_M [mm] "Chip Capacitor, Body 3.2x1.6mm, Height 1.9mm, IPC Low Density"
  rect 1.35x1.9 smd: 1(-1.6,0) 2(1.6,0)
  silkscreen extent -0.55,-0.85 0.55,0.85, body extent -1.7,-0.9 1.7,0.9, height 1.9
CAPC1608X90X35NL15T15 [mm] "Chip Capacitor, 2-Leads, Body 1.60x0.81mm, IPC Medium Density"
  rect 1.05x1 smd: 1(-0.75,0) 2(0.75,0)
  body extent -0.88,-0.48 0.87,0.48, height 0.9
CAPC1608X92X38ML15T08 [mm] "Chip Capacitor, 2-Leads, Body 1.60x0.80mm, IPC Low Density"
  rect 0.95x1.1 smd: 1(-0.725,0) 2(0.725,0)
  body extent -0.87,-0.48 0.87,0.47, height 0.92
CAPC1608X95X35NL15T15 [mm] "Chip Capacitor, 2-Leads, Body 1.60x0.80mm, IPC Medium Density"
  rect 0.9x1 smd: 1(-0.675,0) 2(0.675,0)
  body extent -0.87,-0.48 0.87,0.47, height 0.95
CAPC2013X140X50ML20T25 [mm] "Chip Capacitor, 2-Leads, Body 2.00x1.25mm, IPC Low Density"
  rect 1.5x1.55 smd: 1(-0.9,0) 2(0.9,0)
  body extent -1.1,-0.72 1.1,0.72, height 1.4
CAPC2013X145X48NL20T23 [mm] "Chip Capacitor, 2-Leads, Body 2.00x1.25mm, IPC Medium Density"
  rect 1.3x1.45 smd: 1(-0.825,0) 2(0.825,0)
  body extent -1.1,-0.72 1.1,0.72, height 1.45
CAPC2013X145X50ML20T25 [mm] "Chip Capacitor, 2-Leads, Body 2.00x1.25mm, IPC Low Density"
  rect 1.5x1.55 smd: 1(-0.9,0) 2(0.9,0)
  body extent -1.1,-0.72 1.1,0.72, height 1.45
CAPC2220(5750)230_N [mm] "Chip Capacitor, Body 5.7x5.0mm, Height 2.3mm, IPC Medium Density"
  rect 1.55x5.4 smd: 1(-2.625,0) 2(2.625,0)
  silkscreen extent -1.45,-2.6 1.45,2.6, body extent -3.05,-2.7 3.05,2.7, height 2.3
CAPC3216X180X50NL20T25 [mm] "Chip Capacitor, 2-Leads, Body 3.40x1.80mm, IPC Medium Density"
  rect 1.3x1.8 smd: 1(-1.4,0) 2(1.4,0)
  silkscreen extent -0.35,-0.8 0.35,0.8, body extent -1.7,-0.9 1.7,0.9, height 1.8
CON_JACK_RJ45_L829-1J1T-43 [mm] "CONN MAGJACK 1PORT 1000 BASE-T CON_JACK_RJ45_L829-1J1T-43"
  round 2.083 hole 1.575: 0(-1.27,6.35) 0(16.31,6.35)
  oct 1.422x1.422 hole 0.89: 1(12.595,12.95)
  round 1.422 hole 0.89: 2(10.565,12.95) 3(8.535,12.95) 4(6.505,12.95) 5(4.475,12.95) 6(2.445,12.95) 7(13.62,15.49) 8(11.59,15.49) 9(9.56,15.49) 10(5.48,15.49) 11(3.45,15.49) 12(1.42,15.49)
  round 1.905 hole 1.27: 13(15.04,0) 14(15.04,-2.54) 15(0,2.54) 16(0,0) 17(0,-2.54)
  round 3.3 hole 3.3 unplated: ""(2.69,6.35) ""(12.35,6.35)
  silkscreen extent -1.58,-6.57 16.62,17.41, body extent -2.67,-7.37 17.71,17.14, height 12.65
"CON_TAG TC2050 10P NO LEGS" [mil] "CON TAG CONNECT PLUG  OF NAILS VICTIM AND PLUG BODY"
  round 31 smd paste-40: 1(-100,-25) 2(-50,-25) 3(0,-25) 4(50,-25) 5(100,-25) 6(100,25) 7(50,25) 8(0,25) 9(-50,25) 10(-100,25)
  round 39.37 hole 39.37 unplated: A(-150,0) B(150,40) C(150,-40)
  Top Layer 1 _Signal keep-out region: -100.04,-24.96 99.96,-24.96 99.96,25.04 -100.04,25.04
  silkscreen extent -207,-110 207,87
CONN-TH_2P-P7.62_DB910-7.62-2P [mm]
  round 2.8 hole 1.9 paste-2539.97 mask+0.051: 1(-3.51,0.814) 2(4.11,0.814)
  silkscreen extent -7.99,-6.49 7.99,6.16
CRCW0402-e3_MFG [mm] "Recommended Land Pattern"
  rect 0.4x0.6 smd paste+0 mask+0: 1(-0.45,0) 2(0.45,0)
  silkscreen extent -0.55,-0.68 0.55,0.67, body extent -0.5,-0.25 0.5,0.25, height 0.35
CRYSTAL-SMD_4P-L3.2-W2.5-BL [mm]
  rect 1.4x1.2 smd paste+0 mask+0.051: 1(-0.986,-0.736) 2(1.214,-0.736) 3(1.214,0.964) 4(-0.986,0.964)
  silkscreen extent -2.14,-1.79 2.14,1.79
DFN1006-2L-RD [mm]
  rect 0.5x0.6 smd paste+0 mask+0.051: 1(-0.35,0) 2(0.45,0)
  silkscreen extent -0.85,-0.5 0.85,0.5
DFN2510-10_L2.5-W1.0-P0.50-BL [mm]
  rect 0.2x0.665 smd paste-100 mask+0.051: 1(-1,-0.258) 2(-0.5,-0.258) 4(0.5,-0.258) 5(1,-0.258) 6(1,0.608) 7(0.5,0.608) 9(-0.5,0.608) 10(-1,0.608)
  rect 0.4x0.665 smd paste-100 mask+0.051: 3(0,-0.258) 8(0,0.608)
  silkscreen extent -1.33,-0.94 1.33,0.75
DIO_LED_DUAL_553-0123 [mil] "FOOTPRINT DUAL LED 550-0XXX GREEN/YELLOW"
  round 60 hole 43: 1(-50,-50) 2(-50,50) 3(50,-50) 4(50,50)
  silkscreen extent -215,-92 102,92, body extent -327,-85 95,85, height 380
FAIR-SOD-323_V [mm] "SODFL, 2-Leads, Body 1.25x1.7mm"
  rect 1.05x0.55 smd: 1(-1.4,0) 2(1.4,0)
  silkscreen extent -0.85,-0.62 2.42,0.63, body extent -1.25,-0.63 1.25,0.63, height 1
FBGA-100_14x18 [mm] "BGA, 100-Leads, Body 14x18mm, Pitch 1mm"
  round 0.45 smd mask+0.05: A1(-4.5,8) A2(-3.5,8) A9(3.5,8) A10(4.5,8) B1(-4.5,7) B10(4.5,7) D2(-3.5,5) D3(-2.5,5) D4(-1.5,5) D5(-0.5,5) D6(0.5,5) D7(1.5,5) D8(2.5,5) D9(3.5,5) E2(-3.5,4) E3(-2.5,4) E4(-1.5,4) E5(-0.5,4) E6(0.5,4) E7(1.5,4) E8(2.5,4) E9(3.5,4) F2(-3.5,3) F3(-2.5,3) F4(-1.5,3) F5(-0.5,3) F6(0.5,3) F7(1.5,3) F8(2.5,3) F9(3.5,3) G2(-3.5,2) G3(-2.5,2) G4(-1.5,2) G5(-0.5,2) G6(0.5,2) G7(1.5,2) G8(2.5,2) G9(3.5,2) H2(-3.5,1) H3(-2.5,1) H4(-1.5,1) H5(-0.5,1) H6(0.5,1) H7(1.5,1) H8(2.5,1) H9(3.5,1) J2(-3.5,0) J3(-2.5,0) J4(-1.5,0) J5(-0.5,0) J6(0.5,0) J7(1.5,0) J8(2.5,0) J9(3.5,0) K2(-3.5,-1) K3(-2.5,-1) K4(-1.5,-1) K5(-0.5,-1) K6(0.5,-1) K7(1.5,-1) K8(2.5,-1) K9(3.5,-1) L2(-3.5,-2) L3(-2.5,-2) L4(-1.5,-2) L5(-0.5,-2) L6(0.5,-2) L7(1.5,-2) L8(2.5,-2) L9(3.5,-2) M2(-3.5,-3) M3(-2.5,-3) M4(-1.5,-3) M5(-0.5,-3) M6(0.5,-3) M7(1.5,-3) M8(2.5,-3) M9(3.5,-3) N2(-3.5,-4) N3(-2.5,-4) N4(-1.5,-4) N5(-0.5,-4) N6(0.5,-4) N7(1.5,-4) N8(2.5,-4) N9(3.5,-4) P2(-3.5,-5) P3(-2.5,-5) P4(-1.5,-5) P5(-0.5,-5) P6(0.5,-5) P7(1.5,-5) P8(2.5,-5) P9(3.5,-5) T1(-4.5,-7) T10(4.5,-7) U1(-4.5,-8) U2(-3.5,-8) U9(3.5,-8) U10(4.5,-8)
  silkscreen extent -7.25,-9.25 7.25,9.25, body extent -7,-9 7,9, height 1.4
FBGA-153_L13.0-W11.5-P0.50_KLMAG1JETD-B041 [mm]
  round 0.25 smd mask+0.025: A1(-3.06,3.124) A2(-2.56,3.124) A3(-2.06,3.124) A4(-1.56,3.124) A5(-1.06,3.124) A6(-0.56,3.124) A7(-0.06,3.124) A8(0.44,3.124) A9(0.94,3.124) A10(1.44,3.124) A11(1.94,3.124) A12(2.44,3.124) A13(2.94,3.124) A14(3.44,3.124) B1(-3.06,2.624) B2(-2.56,2.624) B3(-2.06,2.624) B4(-1.56,2.624) B5(-1.06,2.624) B6(-0.56,2.624) B7(-0.06,2.624) B8(0.44,2.624) B9(0.94,2.624) B10(1.44,2.624) B11(1.94,2.624) B12(2.44,2.624) B13(2.94,2.624) B14(3.44,2.624) C1(-3.06,2.124) C2(-2.56,2.124) C3(-2.06,2.124) C4(-1.56,2.124) C5(-1.06,2.124) C6(-0.56,2.124) C7(-0.06,2.124) C8(0.44,2.124) C9(0.94,2.124) C10(1.44,2.124) C11(1.94,2.124) C12(2.44,2.124) C13(2.94,2.124) C14(3.44,2.124) D1(-3.06,1.624) D2(-2.56,1.624) D3(-2.06,1.624) D4(-1.56,1.624) D12(2.44,1.624) D13(2.94,1.624) D14(3.44,1.624) E1(-3.06,1.124) E2(-2.56,1.124) E3(-2.06,1.124) E5(-1.06,1.124) E6(-0.56,1.124) E7(-0.06,1.124) E8(0.44,1.124) E9(0.94,1.124) E10(1.44,1.124) E12(2.44,1.124) E13(2.94,1.124) E14(3.44,1.124) F1(-3.06,0.624) F2(-2.56,0.624) F3(-2.06,0.624) F5(-1.06,0.624) F10(1.44,0.624) F12(2.44,0.624) F13(2.94,0.624) F14(3.44,0.624) G1(-3.06,0.124) G2(-2.56,0.124) G3(-2.06,0.124) G5(-1.06,0.124) G10(1.44,0.124) G12(2.44,0.124) G13(2.94,0.124) G14(3.44,0.124) H1(-3.06,-0.376) H2(-2.56,-0.376) H3(-2.06,-0.376) H5(-1.06,-0.376) H10(1.44,-0.376) H12(2.44,-0.376) H13(2.94,-0.376) H14(3.44,-0.376) J1(-3.06,-0.876) J2(-2.56,-0.876) J3(-2.06,-0.876) J5(-1.06,-0.876) J10(1.44,-0.876) J12(2.44,-0.876) J13(2.94,-0.876) J14(3.44,-0.876) K1(-3.06,-1.376) K2(-2.56,-1.376) K3(-2.06,-1.376) K5(-1.06,-1.376) K6(-0.56,-1.376) K7(-0.06,-1.376) K8(0.44,-1.376) K9(0.94,-1.376) K10(1.44,-1.376) K12(2.44,-1.376) K13(2.94,-1.376) K14(3.44,-1.376) L1(-3.06,-1.876) L2(-2.56,-1.876) L3(-2.06,-1.876) L12(2.44,-1.876) L13(2.94,-1.876) L14(3.44,-1.876) M1(-3.06,-2.376) M2(-2.56,-2.376) M3(-2.06,-2.376) M4(-1.56,-2.376) M5(-1.06,-2.376) M6(-0.56,-2.376) M7(-0.06,-2.376) M8(0.44,-2.376) M9(0.94,-2.376) M10(1.44,-2.376) M11(1.94,-2.376) M12(2.44,-2.376) M13(2.94,-2.376) M14(3.44,-2.376) N1(-3.06,-2.876) N2(-2.56,-2.876) N3(-2.06,-2.876) N4(-1.56,-2.876) N5(-1.06,-2.876) N6(-0.56,-2.876) N7(-0.06,-2.876) N8(0.44,-2.876) N9(0.94,-2.876) N10(1.44,-2.876) N11(1.94,-2.876) N12(2.44,-2.876) N13(2.94,-2.876) N14(3.44,-2.876) P1(-3.06,-3.376) P3(-2.06,-3.376) P4(-1.56,-3.376) P5(-1.06,-3.376) P6(-0.56,-3.376) P7(-0.06,-3.376) P8(0.44,-3.376) P9(0.94,-3.376) P10(1.44,-3.376) P11(1.94,-3.376) P12(2.44,-3.376) P13(2.94,-3.376) P14(3.44,-3.376)
  round 0.203 smd mask+0.025: P2(-2.56,-3.376)
  silkscreen extent -6.03,-6.73 6.03,6.73
FILTER-SMD_4P-L2.0-W1.3-BL_DLW21 [mm]
  rect 0.9x0.4 smd paste+0 mask+0.051: 1(-0.624,-0.4) 2(1.076,-0.4) 3(1.076,0.4) 4(-0.624,0.4)
  silkscreen extent -1.65,-0.85 1.53,0.85
FP-0402-L_1_0_0_05-W_0_5-MFG [mm]
  rect 0.45x0.5 smd paste+0 mask+0: 1(-0.475,0) 2(0.475,0)
  silkscreen extent -0.53,-0.66 0.53,0.65, body extent -0.8,-0.38 0.8,0.38, height 0.25
FP-0402-L_1_0_1-W_0_5_0_1-MFG [mm]
  rect 0.6x0.5 smd paste+0 mask+0: 1(-0.55,0) 2(0.55,0)
  silkscreen extent -0.55,-0.7 0.55,0.7, body extent -0.95,-0.4 0.95,0.4, height 0.25
FP-477AB-IPC_C [mm]
  rect 1.006x0.392 smd paste+0 mask+0: 1(-1,0)
  rrect100% 1.006x0.392 smd paste+0 mask+0: 2(1,0)
  silkscreen extent -1.46,-0.65 0.85,0.82, body extent -1.6,-0.72 1.6,0.72, height 0.25
FP-ABM8AIG-MFG [mm]
  rect 1.4x1.2 smd paste+0 mask+0: 1(-1.1,-0.8) 2(1.1,-0.8) 3(1.1,0.8) 4(-1.1,0.8)
  silkscreen extent -2.47,-1.8 1.65,1.8, body extent -1.9,-1.5 1.9,1.5, height 0.25
FP-AC0402-IPC_B [mm]
  rect 0.615x0.572 smd paste+0 mask+0: 1(-0.429,0) 2(0.429,0)
  silkscreen extent -0.74,-0.69 0.74,0.69, body extent -0.89,-0.44 0.89,0.44, height 0.25
FP-AC0402-IPC_C [mm]
  rect 0.515x0.472 smd paste+0 mask+0: 1(-0.379,0) 2(0.379,0)
  silkscreen extent -0.64,-0.67 0.64,0.67, body extent -0.74,-0.38 0.74,0.38, height 0.25
FP-AC0402-MFG [mm]
  rect 0.5x0.6 smd paste+0 mask+0: 1(-0.5,0) 2(0.5,0)
  silkscreen extent -0.5,-0.67 0.5,0.67, body extent -0.85,-0.4 0.85,0.4, height 0.25
FP-AC0603-IPC_B [mm]
  rect 0.859x0.912 smd paste+0 mask+0: 1(-0.777,0) 2(0.777,0)
  silkscreen extent -1.21,-0.86 1.21,0.86, body extent -1.46,-0.71 1.46,0.71, height 0.25
FP-AC0603-IPC_C [mm]
  rect 0.659x0.812 smd paste+0 mask+0: 1(-0.677,0) 2(0.677,0)
  silkscreen extent -1.01,-0.85 1.01,0.85, body extent -0.8,-0.4 0.8,0.4, height 0.55
FP-AF0201-MFG [mm]
  rect 0.35x0.4 smd paste+0 mask+0: 1(-0.325,0) 2(0.325,0)
  silkscreen extent -0.32,-0.62 0.32,0.62, body extent -0.3,-0.15 0.3,0.15, height 0.26
FP-AF0402-IPC_C [mm]
  rect 0.515x0.472 smd paste+0 mask+0: 1(-0.379,0) 2(0.379,0)
  silkscreen extent -0.64,-0.67 0.64,0.67, body extent -0.74,-0.38 0.74,0.38, height 0.25
FP-AF0402-MFG [mm]
  rect 0.5x0.6 smd paste+0 mask+0: 1(-0.5,0) 2(0.5,0)
  silkscreen extent -0.53,-0.73 0.52,0.73, body extent -0.85,-0.4 0.85,0.4, height 0.25
FP-AF0603-IPC_C [mm]
  rect 0.659x0.812 smd paste+0 mask+0: 1(-0.677,0) 2(0.677,0)
  silkscreen extent -1.01,-0.85 1.01,0.85, body extent -1.11,-0.55 1.11,0.55, height 0.25
FP-AF0805-IPC_B [mm]
  rect 1.008x1.362 smd paste+0 mask+0: 1(-0.902,0) 2(0.902,0)
  silkscreen extent -1.41,-1.08 1.41,1.08, body extent -1.66,-0.93 1.66,0.93, height 0.25
FP-AT0402-IPC_B [mm]
  rect 0.66x0.572 smd paste+0 mask+0: 1(-0.426,0) 2(0.426,0)
  silkscreen extent -0.76,-0.69 0.76,0.69, body extent -0.91,-0.44 0.91,0.44, height 0.25
FP-AT0603-IPC_B [mm]
  rect 0.859x0.912 smd paste+0 mask+0: 1(-0.777,0) 2(0.777,0)
  silkscreen extent -1.21,-0.86 1.21,0.86, body extent -1.46,-0.71 1.46,0.71, height 0.25
FP-B12P-XL_LF_SN-MFG [mm]
  rect 2.3x2.3 hole 1.5 paste-2539.97 mask+0: 1(12.5,-1.08)
  round 2.3 hole 1.5 paste-2539.97 mask+0: 2(7.5,-1.08) 3(2.5,-1.08) 4(-2.5,-1.08) 5(-7.5,-1.08) 6(-12.5,-1.08) 7(12.5,4.72) 8(7.5,4.72) 9(2.5,4.72) 10(-2.5,4.72) 11(-7.5,4.72) 12(-12.5,4.72)
  silkscreen extent -15,-7.7 15.72,7.7, body extent -15.1,-7.8 15.1,7.8, height 0.25
FP-BLM18-0_15-t0_6-d1_2-IPC_A [mm]
  rect 1.306x1.058 smd paste+0 mask+0: 1(-0.776,0) 2(0.776,0)
  silkscreen extent -1.43,-0.93 1.43,0.93, body extent -1.93,-1.03 1.93,1.03, height 0.25
FP-C04-052-MFG [mm]
  rect 2x0.6 smd paste+0 mask+0: 1(-4.7,8.255) 2(-4.7,6.985) 3(-4.7,5.715) 4(-4.7,4.445) 5(-4.7,3.175) 6(-4.7,1.905) 7(-4.7,0.635) 8(-4.7,-0.635) 9(-4.7,-1.905) 10(-4.7,-3.175) 11(-4.7,-4.445) 12(-4.7,-5.715) 13(-4.7,-6.985) 14(-4.7,-8.255) 15(4.7,-8.255) 16(4.7,-6.985) 17(4.7,-5.715) 18(4.7,-4.445) 19(4.7,-3.175) 20(4.7,-1.905) 21(4.7,-0.635) 22(4.7,0.635) 23(4.7,1.905) 24(4.7,3.175) 25(4.7,4.445) 26(4.7,5.715) 27(4.7,6.985) 28(4.7,8.255)
  silkscreen extent -6.42,-9.05 3.8,9.05, body extent -5.8,-9.3 5.8,9.3, height 0.25
FP-C04-1007-MFG [mm]
  rect 0.85x1 smd paste+0 mask+0: 1(-0.8,1.05) 3(-0.8,-1.05) 4(0.8,-1.05) 6(0.8,1.05)
  rect 0.85x0.6 smd paste+0 mask+0: 2(-0.8,0) 5(0.8,0)
  silkscreen extent -1.92,-1.95 1.6,1.95, body extent -1.38,-1.73 1.38,1.73, height 0.25
FP-C0201-AB-MFG [mm]
  rect 0.36x0.32 smd paste+0 mask+0: 1(-0.28,0) 2(0.28,0)
  silkscreen extent -0.3,-0.55 0.3,0.55
FP-C0402-BB-MFG [mm]
  rect 0.52x0.52 smd paste+0 mask+0: 1(-0.4,0) 2(0.4,0)
  silkscreen extent -0.5,-0.64 0.5,0.63, body extent -0.5,-0.25 0.5,0.25, height 0.55
FP-C0402C105K8PACTU-MFG [mm]
  rect 0.52x0.52 smd paste+0 mask+0: 1(-0.4,0) 2(0.4,0)
  silkscreen extent -0.67,-0.63 0.67,0.64, body extent -0.8,-0.4 0.8,0.4, height 0.25
FP-C0402C-BB-IPC_B [mm]
  rect 0.661x0.572 smd paste+0 mask+0: 1(-0.406,0) 2(0.406,0)
  silkscreen extent -0.74,-0.69 0.74,0.69, body extent -0.5,-0.25 0.5,0.25, height 0.55
FP-C0603C-CF-MFG [mm]
  rect 0.75x0.9 smd paste+0 mask+0: 1(-0.6,0) 2(0.6,0)
  silkscreen extent -0.87,-0.85 0.88,0.85, body extent -1.2,-0.6 1.2,0.6, height 0.25
FP-C0805C106K3PACTU-MFG [mm]
  rect 0.95x1.35 smd paste+0 mask+0: 1(-0.75,0) 2(0.75,0)
  silkscreen extent -1.1,-1.05 1.1,1.05, body extent -1.4,-0.85 1.4,0.85, height 0.25
FP-C0805C226M8PACTU-MFG [mm]
  rect 0.95x1.35 smd paste+0 mask+0: 1(-0.75,0) 2(0.75,0)
  silkscreen extent -1.22,-1.05 1.22,1.05, body extent -1.4,-0.85 1.4,0.85, height 0.25
FP-C0805C-DN-MFG [mm]
  rect 0.95x1.35 smd paste+0 mask+0: 1(-0.75,0) 2(0.75,0)
  silkscreen extent -1.1,-1.08 1.1,1.07, body extent -1.4,-0.85 1.4,0.85, height 0.25
FP-C1206C-EH-MFG [mm]
  rect 0.95x1.7 smd paste+0 mask+0: 1(-1.4,0) 2(1.4,0)
  silkscreen extent -0.55,-0.9 0.55,0.9, body extent -2,-1 2,1, height 0.25
FP-C2012-125-0_2-IPC_B [mm]
  rect 1.378x1.456 smd paste+0 mask+0: 1(-0.764,0) 2(0.764,0)
  silkscreen extent -1.45,-1.13 1.45,1.13, body extent -1.7,-0.98 1.7,0.98, height 0.25
FP-CB2016-MFG [mm]
  rect 0.6x1.8 smd paste+0 mask+0: 1(-0.8,0) 2(0.8,0)
  silkscreen extent -1.1,-1.27 1.1,1.27, body extent -1.2,-1 1.2,1, height 0.25
FP-CC0201-BA-MFG [mm]
  rect 0.28x0.3 smd paste+0 mask+0: 1(-0.265,0) 2(0.265,0)
  silkscreen extent -0.31,-0.53 0.31,0.52, body extent -0.3,-0.15 0.3,0.15, height 0.33
FP-CC0201-BB-MFG [mm]
  rect 0.28x0.3 smd paste+0 mask+0: 1(-0.265,0) 2(0.265,0)
  silkscreen extent -0.32,-0.53 0.32,0.52, body extent -0.3,-0.15 0.3,0.15, height 0.33
FP-CC0402-CC-MFG [mm]
  rect 0.5x0.5 smd paste+0 mask+0: 1(-0.5,0) 2(0.5,0)
  silkscreen extent -0.53,-0.68 0.52,0.67, body extent -0.95,-0.55 0.95,0.55, height 0.25
FP-CC0402-MFG [mm]
  rect 0.5x0.5 smd paste+0 mask+0: 1(-0.5,0) 2(0.5,0)
  silkscreen extent -0.53,-0.68 0.53,0.67, body extent -0.87,-0.48 0.87,0.48, height 0.25
FP-CC0603-DC-MFG [mm]
  rect 0.9x0.9 smd paste+0 mask+0: 1(-0.7,0) 2(0.7,0)
  silkscreen extent -0.9,-0.83 0.9,0.82, body extent -0.8,-0.4 0.8,0.4, height 1
FP-CGA2B-IPC_B [mm]
  rect 0.372x0.572 smd paste+0 mask+0: 1(-0.55,0) 2(0.55,0)
  silkscreen extent -0.74,-0.69 0.74,0.69, body extent -0.89,-0.44 0.89,0.44, height 0.25
FP-CGA3E-0_3-0_1-IPC_A [mm]
  rect 0.956x1.206 smd paste+0 mask+0: 1(-1.025,0) 2(1.025,0)
  silkscreen extent -0.25,-0.6 0.25,0.6, body extent -2,-1.1 2,1.1, height 0.25
FP-CL03-IPC_C [mm]
  rect 0.354x0.263 smd paste+0 mask+0: 1(-0.254,0) 2(0.254,0)
  silkscreen extent -0.43,-0.57 0.43,0.56, body extent -0.3,-0.15 0.3,0.15, height 0.33
FP-CRCW0402-e3-IPC_A [mm]
  rect 0.668x0.672 smd paste+0 mask+0: 1(-0.502,0) 2(0.502,0)
  silkscreen extent -0.84,-0.74 0.84,0.74, body extent -1.04,-0.54 1.04,0.54, height 0.25
FP-CRCW0402-e3-IPC_B [mm]
  rect 0.568x0.572 smd paste+0 mask+0: 1(-0.452,0) 2(0.452,0)
  silkscreen extent -0.74,-0.69 0.74,0.69, body extent -0.89,-0.44 0.89,0.44, height 0.25
FP-CRCW0402-e3-IPC_C [mm]
  rect 0.468x0.472 smd paste+0 mask+0: 1(-0.402,0) 2(0.402,0)
  silkscreen extent -0.64,-0.67 0.64,0.68, body extent -0.74,-0.38 0.74,0.38, height 0.25
FP-CRCW0402-e3-MFG [mm]
  rect 0.6x0.6 smd paste+0 mask+0: 1(-0.525,0) 2(0.525,0)
  silkscreen extent -0.53,-0.7 0.53,0.7, body extent -0.92,-0.4 0.92,0.4, height 0.25
FP-CRCW0805-e3-IPC_C [mil]
  rect 31.75x51.5 smd paste+0 mask+0: 1(-33.5,0) 2(33.5,0)
  silkscreen extent -3,-25 3,25, body extent -53,-31 53,31, height 10
FP-CRGCQ0402-IPC_C [mm]
  rect 0.56x0.472 smd paste+0 mask+0: 1(-0.376,0) 2(0.376,0)
  silkscreen extent -0.66,-0.67 0.66,0.67, body extent -0.5,-0.25 0.5,0.25, height 0.4
FP-CRGP0402-IPC_C [mm]
  rect 0.56x0.472 smd paste+0 mask+0: 1(-0.426,0) 2(0.426,0)
  silkscreen extent -0.71,-0.67 0.71,0.67, body extent -0.55,-0.25 0.55,0.25, height 0.4
FP-DCK0006A-MFG [mm]
  rrect25% 0.9x0.4 smd paste+0 mask+0: 1(-1.1,0.65) 2(-1.1,0) 3(-1.1,-0.65) 4(1.1,-0.65) 5(1.1,0) 6(1.1,0.65)
  silkscreen extent -1.28,-1.08 0.27,1.52, body extent -1.65,-1.33 1.65,1.33, height 0.25
FP-FDSD0415-MFG [mm]
  rect 1.4x2.4 smd paste+0 mask+0: 1(-1.6,0) 2(1.6,0)
  silkscreen extent -3.1,-2.1 2.1,2.1, body extent -2.4,-2.2 2.4,2.2, height 0.25
FP-GRM15-0_1-MFG [mm]
  rect 0.4x0.5 smd paste+0 mask+0: 1(-0.4,0) 2(0.4,0)
  silkscreen extent -0.55,-0.63 0.55,0.62, body extent -0.7,-0.38 0.7,0.38, height 0.25
FP-GRM21B-0_2-e0_2_0_7-IPC_B [mm]
  rect 1.255x1.456 smd paste+0 mask+0: 1(-0.826,0) 2(0.826,0)
  silkscreen extent -1.45,-1.13 1.45,1.13, body extent -1.7,-0.98 1.7,0.98, height 0.25
FP-GRM21B-0_2-e0_2_0_7-IPC_C [mm]
  rect 1.055x1.356 smd paste+0 mask+0: 1(-0.726,0) 2(0.726,0)
  silkscreen extent -1.25,-1.12 1.25,1.12, body extent -1.35,-0.82 1.35,0.82, height 0.25
FP-GRM31C-0_2-e0_3_0_8-IPC_C [mm]
  rect 1.155x1.706 smd paste+0 mask+0: 1(-1.276,0) 2(1.276,0)
  silkscreen extent -0.4,-0.9 0.4,0.9, body extent -1.95,-1 1.95,1, height 0.25
FP-GRM31C-0_3-e0_3_0_8-IPC_A [mm]
  rect 1.653x2.004 smd paste+0 mask+0: 1(-1.475,0) 2(1.475,0)
  silkscreen extent -0.35,-1 0.35,1, body extent -2.8,-1.5 2.8,1.5, height 0.25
